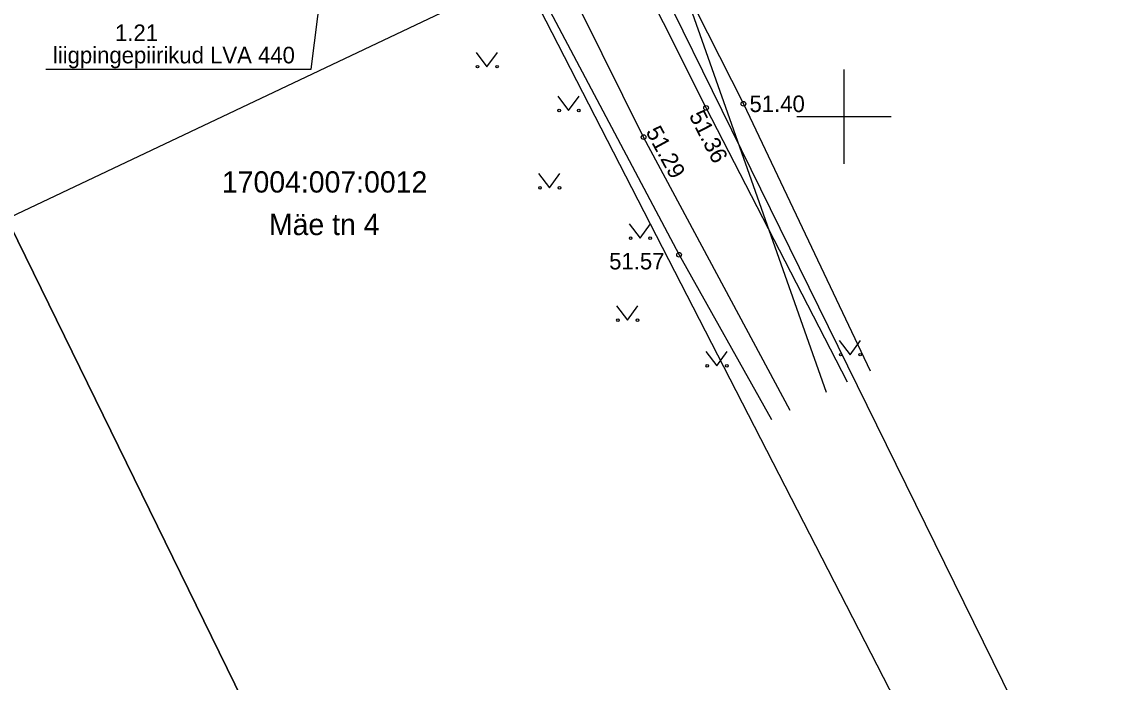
# Model space of a CAD drawing. Extents: x 642747 to 644424, y 6457048 to 6458238.
# Drawn here: x 643665.18 to 643711.66, y 6457476.06 to 6457504.01 of the extents above; entities that cross this region are included whole.
import ezdxf

# ---------------------------------------------------------------- set-up
doc = ezdxf.new("R2010")
doc.units = 0
for name, color, linetype in [('ABIJOONIS', 7, 'Continuous'), ('AED', 7, 'Continuous'), ('HALJASTUS', 7, 'Continuous'), ('JOONSIDE', 7, 'Continuous'), ('KORGUS', 7, 'Continuous'), ('KTRASS', 7, 'Continuous'), ('MOOTPIIR', 7, 'Continuous'), ('PIIR', 7, 'Continuous'), ('TEE', 7, 'Continuous'), ('VORK', 7, 'Continuous')]:
    doc.layers.add(name, color=color, linetype=linetype)

msp = doc.modelspace()

# ---------------------------------------------------------------- linework, layer by layer
at = {"layer": 'ABIJOONIS'}
msp.add_lwpolyline([(643666.191, 6457502.012), (643677.434, 6457502.012), (643679.597, 6457519.088)], dxfattribs=at)
at = {"layer": 'AED'}
msp.add_lwpolyline([(643661.17, 6457502.684), (643676.864, 6457510.301), (643679.691, 6457511.621), (643680.738, 6457512.116), (643683.084, 6457513.29), (643685.931, 6457507.532), (643693.016, 6457494.152), (643696.94, 6457487.172)], dxfattribs=at)
at = {"layer": 'HALJASTUS'}
for p, q in [((643684.416, 6457502.72), (643684.879, 6457502.114)), ((643684.879, 6457502.114), (643685.325, 6457502.72)), ((643687.874, 6457500.864), (643688.338, 6457500.257)), ((643688.338, 6457500.257), (643688.783, 6457500.864)), ((643687.063, 6457497.587), (643687.526, 6457496.981)), ((643687.526, 6457496.981), (643687.972, 6457497.587)), ((643690.903, 6457495.458), (643691.367, 6457494.851)), ((643691.367, 6457494.851), (643691.812, 6457495.458)), ((643690.364, 6457491.99), (643690.828, 6457491.383)), ((643690.828, 6457491.383), (643691.273, 6457491.99)), ((643699.8, 6457490.527), (643700.263, 6457489.92)), ((643700.263, 6457489.92), (643700.709, 6457490.527)), ((643694.151, 6457490.052), (643694.614, 6457489.445)), ((643694.614, 6457489.445), (643695.06, 6457490.052))]:
    msp.add_line(p, q, dxfattribs=at)
msp.add_lwpolyline([(643689.657, 6457512.556), (643695.741, 6457500.542), (643701.116, 6457489.232)], dxfattribs=at)
for centre in [(643684.478, 6457502.114), (643685.307, 6457502.114), (643687.937, 6457500.257), (643688.766, 6457500.257), (643687.125, 6457496.981), (643687.954, 6457496.981), (643690.966, 6457494.851), (643691.795, 6457494.851), (643690.427, 6457491.383), (643691.256, 6457491.383), (643699.862, 6457489.92), (643700.691, 6457489.92), (643694.213, 6457489.445), (643695.042, 6457489.445)]:
    msp.add_circle(centre, 0.055, dxfattribs=at)
at = {"layer": 'KORGUS'}
for centre in [(643695.741, 6457500.542), (643694.164, 6457500.367), (643691.515, 6457499.131), (643693.016, 6457494.152)]:
    msp.add_circle(centre, 0.1, dxfattribs=at)
at = {"layer": 'KTRASS'}
msp.add_lwpolyline([(643699.268, 6457488.32), (643689.411, 6457516.213)], dxfattribs=at)
at = {"layer": 'MOOTPIIR'}
msp.add_lwpolyline([(643525.446, 6457467.559), (643537.447, 6457435.458), (643944.848, 6457628.51), (644046.626, 6457529.09), (644067.022, 6457529.09), (644138.408, 6457598.401), (644075.1, 6457775.215), (644046.02, 6457752.582), (644092.466, 6457611.94), (644070.657, 6457576.375), (644041.981, 6457570.717), (643942.223, 6457662.862)], close=True, dxfattribs=at)
at = {"layer": 'PIIR'}
for points in [[(643750.22, 6457457.29), (643778.12, 6457470.27), (643782.64, 6457472.43), (643747.54, 6457544.43), (643690.88, 6457517.6), (643689.08, 6457511.97), (643715.74, 6457457.75), (643719.34, 6457459.43), (643726.21, 6457446.01)], [(643682.44, 6457513.67), (643660.72, 6457503.45), (643695.86, 6457431.74), (643714.94, 6457440.75), (643708.5, 6457454.34), (643712.07, 6457456.04)], [(643660.72, 6457503.45), (643611.69, 6457480.38), (643646.88, 6457409.03), (643695.86, 6457431.74)]]:
    msp.add_lwpolyline(points, close=True, dxfattribs=at)
at = {"layer": 'TEE'}
for points in [[(643700.146, 6457488.754), (643694.164, 6457500.367), (643688.749, 6457511.18), (643688.186, 6457515.45), (643689.023, 6457518.609)], [(643697.728, 6457487.561), (643691.515, 6457499.131), (643686.266, 6457509.7), (643684.68, 6457514.253), (643682.941, 6457515.576)]]:
    msp.add_lwpolyline(points, dxfattribs=at)
at = {"layer": 'VORK'}
for p, q in [((643700, 6457502), (643700, 6457498)), ((643698, 6457500), (643702, 6457500))]:
    msp.add_line(p, q, dxfattribs=at)

# ---------------------------------------------------------------- texts
at = {"layer": 'ABIJOONIS'}
msp.add_text('liigpingepiirikud LVA 440', height=0.7, dxfattribs=at).set_placement((643666.489, 6457502.254))
at = {"layer": 'JOONSIDE'}
msp.add_text('1.21', height=0.7, dxfattribs=at).set_placement((643669.121, 6457503.2))
at = {"layer": 'KORGUS'}
for s, p in [(' 51.40', (643695.741, 6457500.192)), (' 51.57', (643689.796, 6457493.529))]:
    msp.add_text(s, height=0.7, dxfattribs=at).set_placement(p)
for s, rotation, p in [(' 51.36', 297.0767, (643693.304, 6457500.275)), (' 51.29', 298.412, (643691.463, 6457499.594))]:
    msp.add_text(s, height=0.7, rotation=rotation, dxfattribs=at).set_placement(p)
at = {"layer": 'PIIR'}
for s, p in [('17004:007:0012', (643673.649, 6457496.784)), ('Mäe tn 4', (643675.643, 6457494.984))]:
    msp.add_text(s, height=0.9, dxfattribs=at).set_placement(p)

doc.saveas('drawing.dxf')
